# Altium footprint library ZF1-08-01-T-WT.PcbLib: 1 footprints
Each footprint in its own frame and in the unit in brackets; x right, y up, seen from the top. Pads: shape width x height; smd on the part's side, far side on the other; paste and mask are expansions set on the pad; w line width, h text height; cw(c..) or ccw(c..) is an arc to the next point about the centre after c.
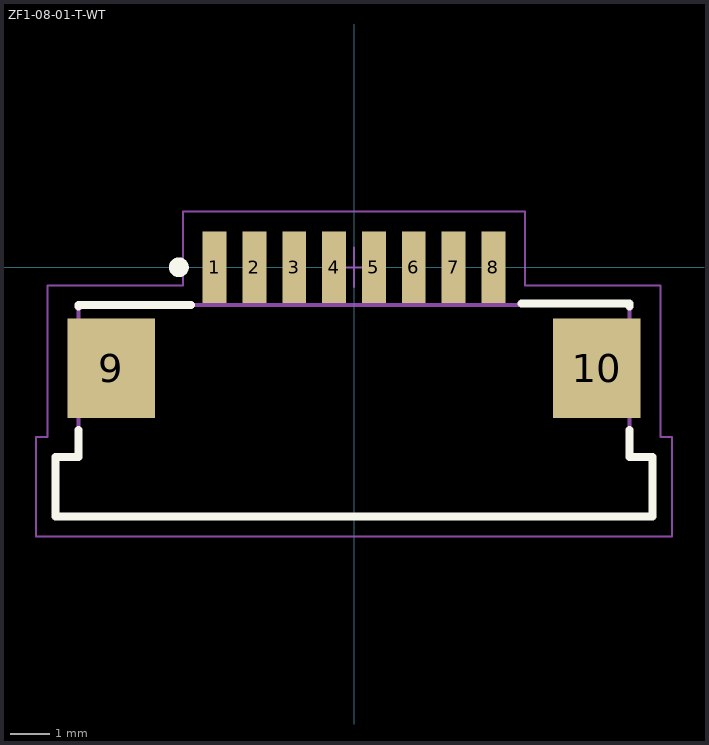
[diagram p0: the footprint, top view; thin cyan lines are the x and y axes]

## ZF1-08-01-T-WT [mm] "1.00mm pitch, 8 pin, ZIF FPC socket; bottom contact"
height 2.54
pads (10):
  rect 0.6x1.8 smd mask+0: 1(-3.5,0) 2(-2.5,0) 3(-1.5,0) 4(-0.5,0) 5(0.5,0) 6(1.5,0) 7(2.5,0) 8(3.5,0)
  rect 2.2x2.5 smd mask+0: 9(-6.1,-2.54) 10(6.1,-2.54)
Top Overlay:
  circle w0.25: c-4.4,0 r0.125
  lines w0.2: -6.921,-4.09 -6.921,-4.763 -7.493,-4.763 -7.493,-6.261 7.493,-6.261 7.493,-4.763 6.921,-4.763 6.921,-4.09 ; -6.921,-0.99 -6.921,-0.953 -4.1,-0.953 ; 4.209,-0.914 6.921,-0.914 6.921,-0.99
Mechanical 12:
  lines w0.001: -7.493,-6.261 -7.493,-4.763 -6.921,-4.763 -6.921,-0.953 6.921,-0.953 6.921,-4.763 7.493,-4.763 7.493,-6.261 -7.493,-6.261
Mechanical 13:
  lines w0.1: -7.493,-6.261 -7.493,-4.763 -6.921,-4.763 -6.921,-0.953 6.921,-0.953 6.921,-4.763 7.493,-4.763 7.493,-6.261 -7.493,-6.261
  text ".Designator" at 0,0 h1.52
Mechanical 15:
  lines w0.05: -0.5,0 0.5,0 ; 0,-0.5 0,0.5 ; -7.993,-6.761 -7.993,-4.263 -7.7,-4.263 -7.7,-0.453 -4.3,-0.453 -4.3,1.4 4.3,1.4 4.3,-0.453 7.7,-0.453 7.7,-4.263 7.993,-4.263 7.993,-6.761 -7.993,-6.761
